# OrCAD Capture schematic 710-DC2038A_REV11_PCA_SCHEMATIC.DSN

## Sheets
1 PAGE2: size Custom; note: 35V/3.2A MULTI-CELL STEP-DOWN BATTERY CHARGER WITH POWERPATH AND I2C TELEMETRY
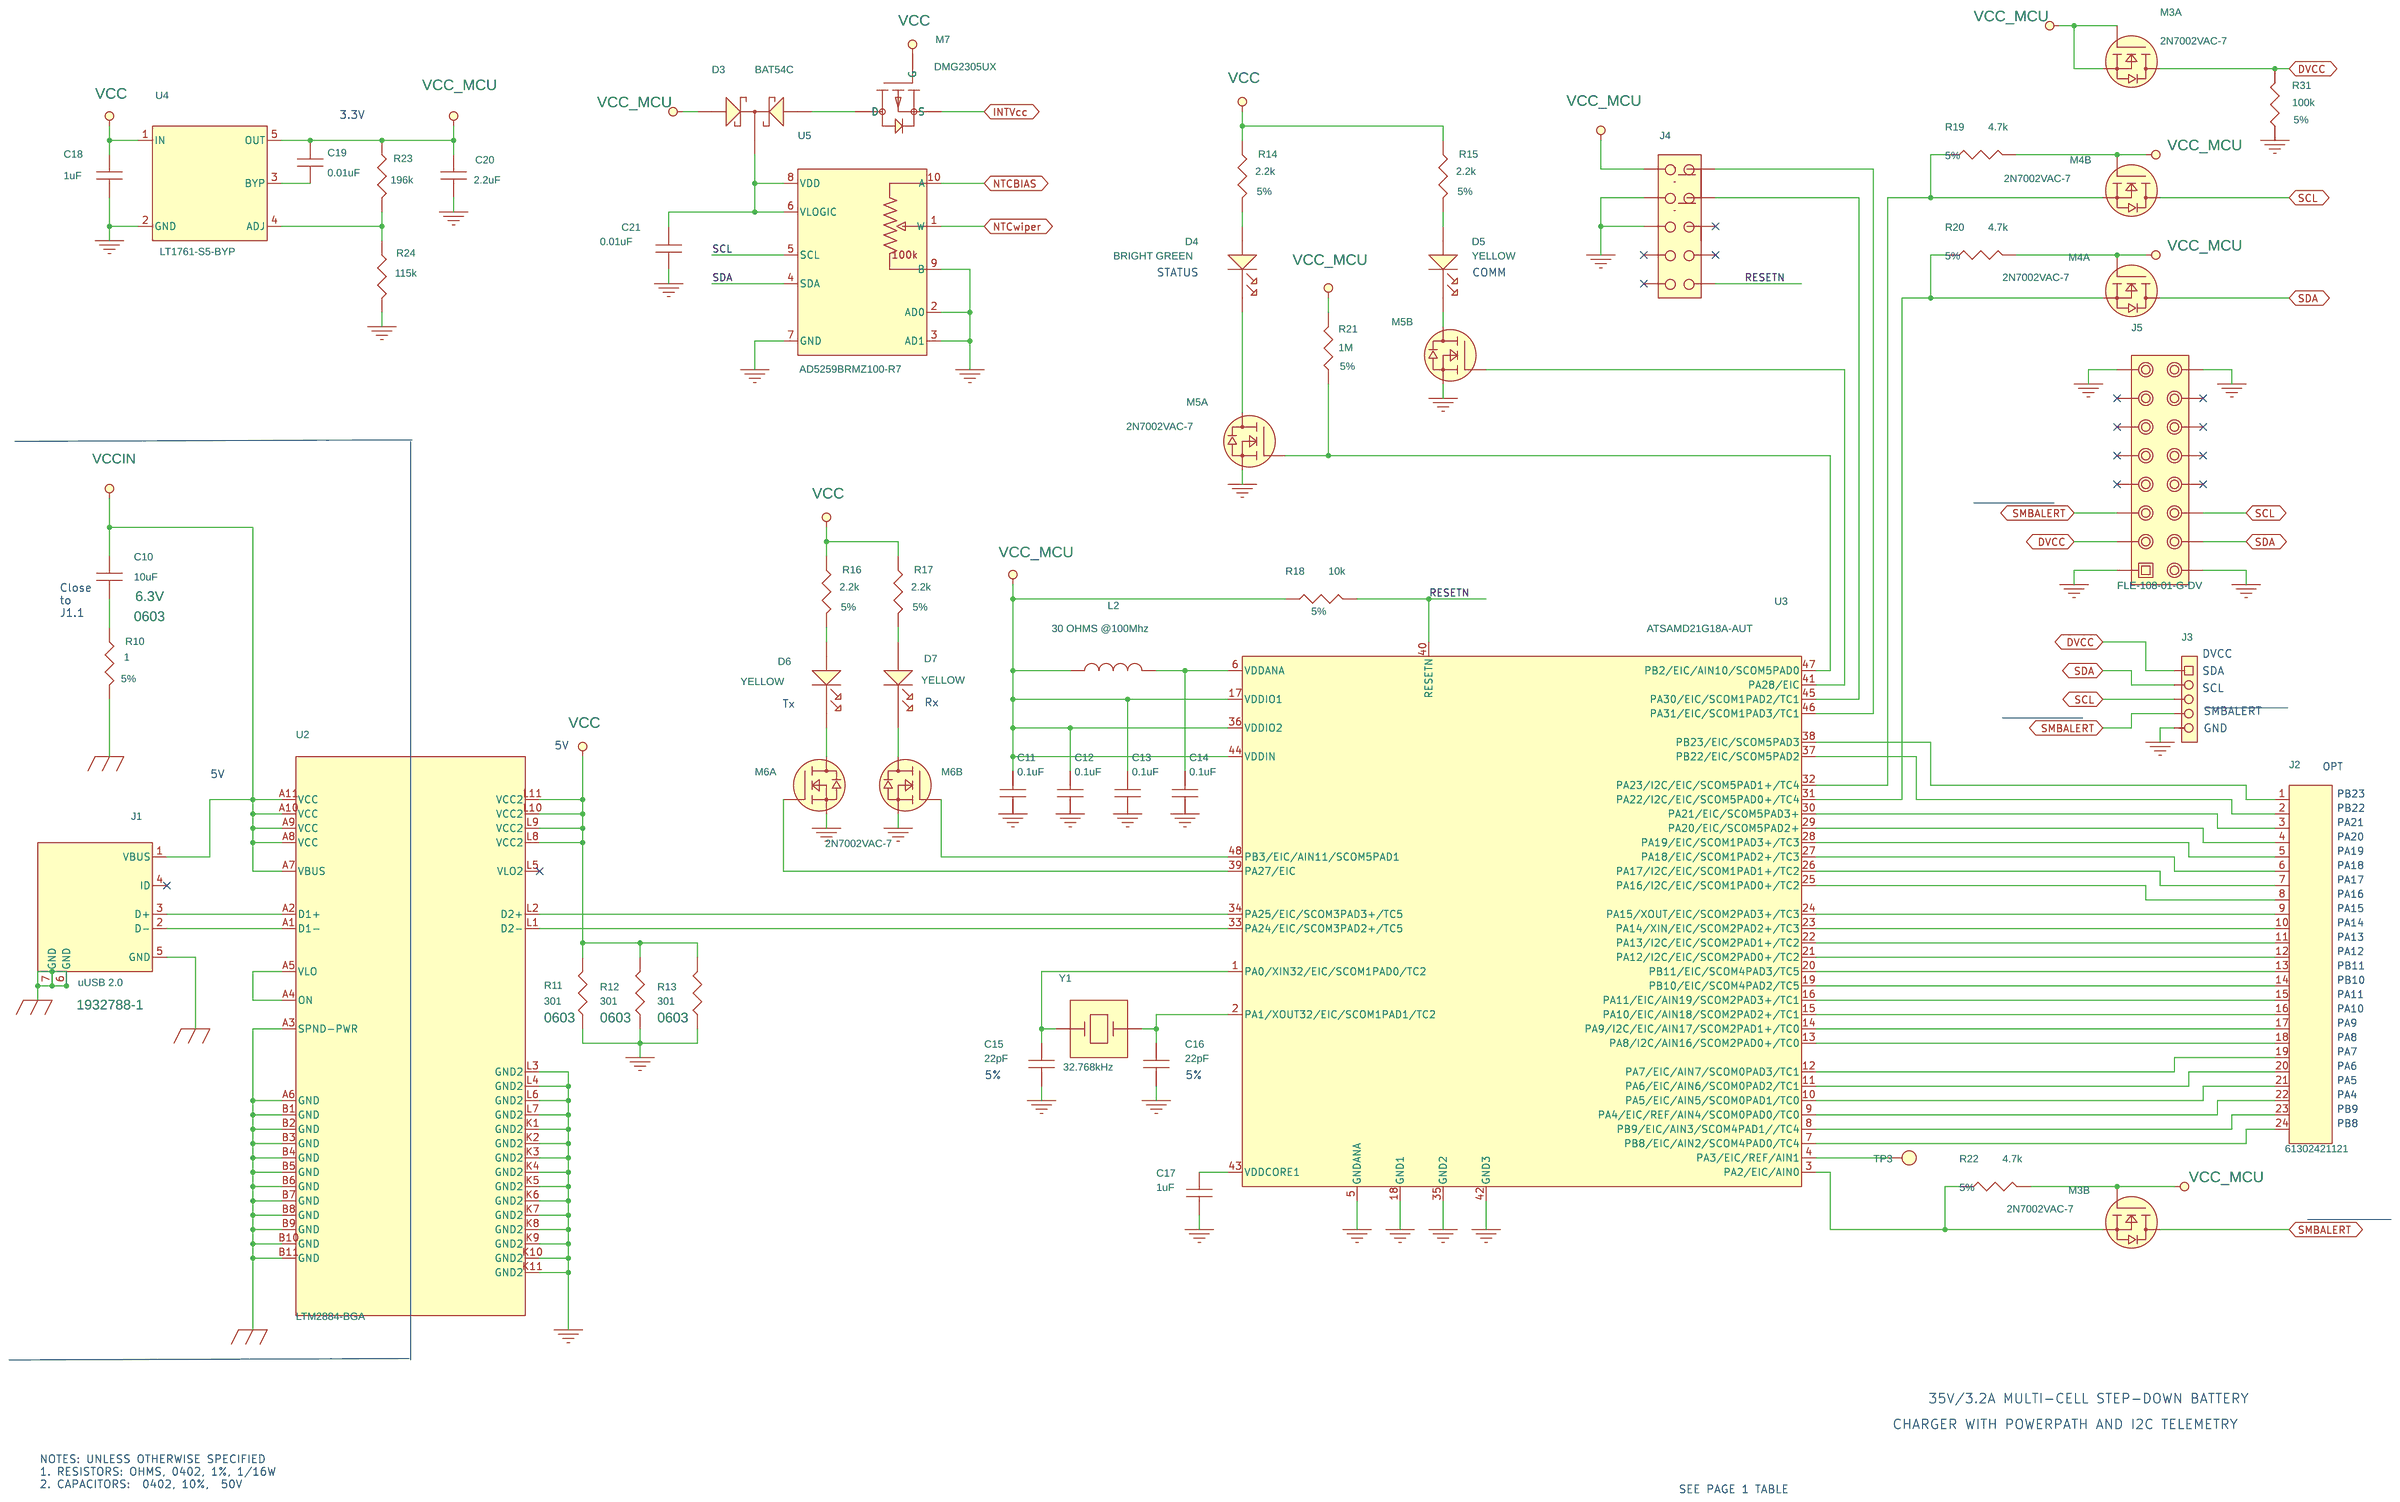
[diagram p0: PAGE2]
2 PAGE 1: size C
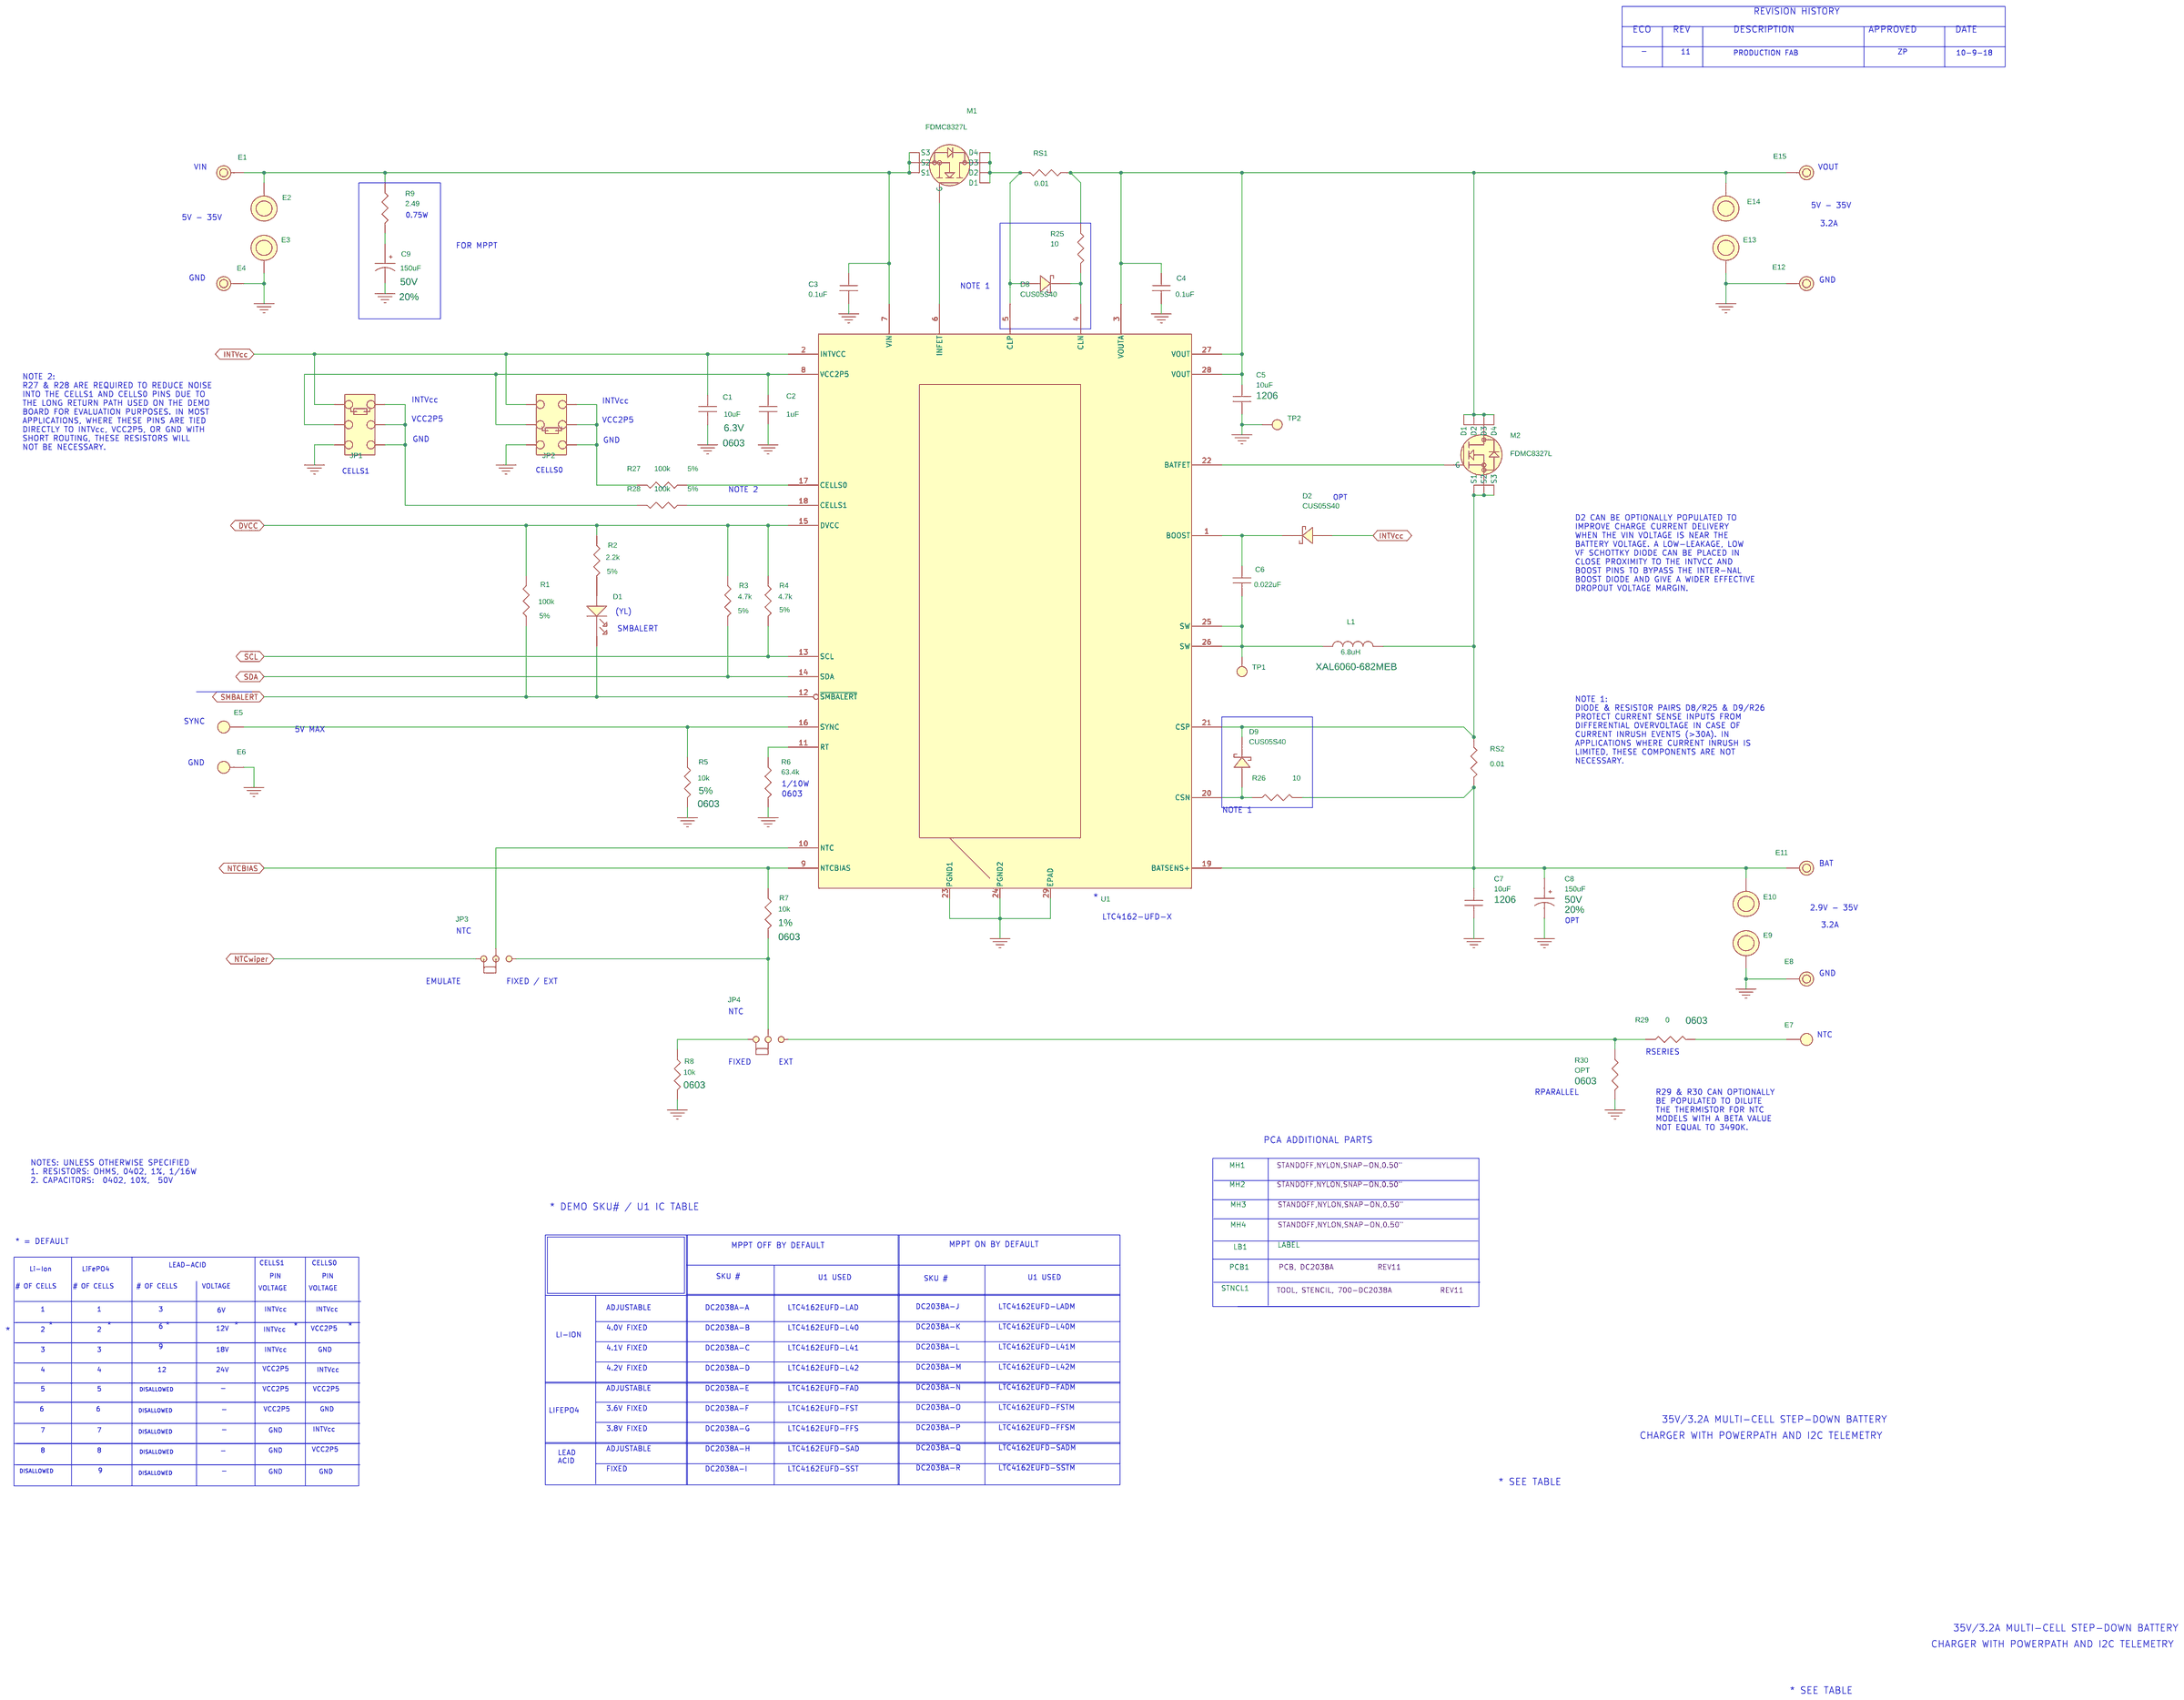
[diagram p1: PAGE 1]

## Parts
sheet PAGE2
C10  10uF  [CC0603N]
C11  0.1uF  [CC0402N]
C12  0.1uF  [CC0402N]
C13  0.1uF  [CC0402N]
C14  0.1uF  [CC0402N]
C15  22pF  [CC0402N]
C16  22pF  [CC0402N]
C17  1uF  [CC0402N]
C18  1uF  [CC0402N]
C19  0.01uF  [CC0402N]
C20  2.2uF  [CC0402N]
C21  0.01uF  [CC0402N]
D3  BAT54C  [SOT23-3M]
D4  BRIGHT GREEN  [LED_0603]
D5  YELLOW  [LED_0603]
D6  YELLOW  [LED_0603]
D7  YELLOW  [LED_0603]
J1  uUSB 2.0  [TE-1932788-1]
J2  61302421121  [WURTH-HDR-2.54MM-DUAL]
J3  HDR  [HDR-TSW-105-07-L-S]
J4  HDR  [WURTH-62201021121]
J5  SOCKET  [SAMTEC-FLE-108-01-XX-DV]
L2  30 OHMS @100Mhz  [IND0805N]
M3  2N7002VAC-7  [SOT563-6N]  (sections A,B)
M4  2N7002VAC-7  [SOT563-6N]  (sections A,B)
M5  2N7002VAC-7  [SOT563-6N]  (sections A,B)
M6  2N7002VAC-7  [SOT563-6N]  (sections A,B)
M7  DMG2305UX  [SOT23-3M]
R10  1  [CR0402M]
R11  301  [CR0603N]
R12  301  [CR0603N]
R13  301  [CR0603N]
R14  2.2k  [CR0402M]
R15  2.2k  [CR0402M]
R16  2.2k  [CR0402M]
R17  2.2k  [CR0402M]
R18  10k  [CR0402N]
R19  4.7k  [CR0402M]
R20  4.7k  [CR0402M]
R21  1M  [CR0402N]
R22  4.7k  [CR0402M]
R23  196k  [CR0603N]
R24  115k  [CR0603N]
R31  100k  [CR0402M]
TP3  TEST PAD  [PADSTYLE2]
U2  LTM2884-BGA  [LTM-BGA-44-1881]
U3  ATSAMD21G18A-AUT  [MICROCHIP-TQFP48-NO_TAB]
U4  LT1761-S5-BYP  [LTC-S5-5-1635]
U5  AD5259BRMZ100-R7  [AD5259BRMZ100-R7]
Y1  32.768kHz  [ECX-31B]
sheet PAGE 1
C1  10uF  [CC0603N]
C2  1uF  [CC0402M]
C3  0.1uF  [CC0402M]
C4  0.1uF  [CC0402M]
C5  10uF  [CC1206N]
C6  0.022uF  [CC0402M]
C7  10uF  [CC1206N]
C8  150uF  [CAP_EEFK_G]
C9  150uF  [CAP_EEFK_G]
D1  SUPER YELLOW  [LED_0603]
D2  CUS05S40  [SOD-323N]
D8  CUS05S40  [SOD-323N]
D9  CUS05S40  [SOD-323N]
E1  TEST POINT  [MILLMAX2501]
E2  BANANA JACK  [KEY-575-4]
E3  BANANA JACK  [KEY-575-4]
E4  TEST POINT  [MILLMAX2501]
E5  TEST POINT  [MILLMAX2308]
E6  TEST POINT  [MILLMAX2308]
E7  TEST POINT  [MILLMAX2308]
E8  TEST POINT  [MILLMAX2501]
E9  BANANA JACK  [KEY-575-4]
E10  BANANA JACK  [KEY-575-4]
E11  TEST POINT  [MILLMAX2501]
E12  TEST POINT  [MILLMAX2501]
E13  BANANA JACK  [KEY-575-4]
E14  BANANA JACK  [KEY-575-4]
E15  TEST POINT  [MILLMAX2501]
JP1  HDR  [CON6_2X3_WURTH_62130621021_SMT]
JP2  HDR  [CON6_2X3_WURTH_62130621021_SMT]
JP3  HDR.  [HD1X3-079]
JP4  HDR.  [HD1X3-079]
L1  6.8uH  [COILCRAFT-XAL6060]
LB1  LABEL  [895-0154_REV01]
M1  FDMC8327L  [FAIRCHILD-MLP3.3X3.3]
M2  FDMC8327L  [FAIRCHILD-MLP3.3X3.3]
MH1  STANDOFF  [KEYSTONE_8829-8834]
MH2  STANDOFF  [KEYSTONE_8829-8834]
MH3  STANDOFF  [KEYSTONE_8829-8834]
MH4  STANDOFF  [KEYSTONE_8829-8834]
PCB1  PCB, DC2038A
R1  100k  [CR0402M]
R2  2.2k  [CR0402M]
R3  4.7k  [CR0402M]
R4  4.7k  [CR0402M]
R5  10k  [CR0603N]
R6  63.4k  [CR0603N]
R7  10k  [CR0603N]
R8  10k  [CR0603N]
R9  2.49  [CR1206N]
R25  10  [CR0402N]
R26  10  [CR0402N]
R27  100k  [CR0402M]
R28  100k  [CR0402M]
R29  0  [CR0603N]
R30  OPT  [CR0603N]
RS1  0.01  [RES-PRL0816]
RS2  0.01  [RES-PRL0816]
STNCL1  TOOL, STENCIL, 700-DC2038A
TP1  TEST PAD  [PADSTYLE2]
TP2  TEST PAD  [PADSTYLE2]
U1  LTC4162-UFD-FADM  [LTC-UFD-28-1712]
XJP1  SHUNT
XJP2  SHUNT
XJP3  SHUNT
XJP4  SHUNT

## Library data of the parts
C1 C10 = CAP: CAP.,10uF,X5R,6.3V,20%,0603; CLASS: DISCRETE; Dielectric Type: X5R; Manufacturer: MURATA; Manufacturer PN: GRM188R60J106ME47D; PART_NUMBER: 150-3401; Package Size: 0603; Package Type: SMD; Rated Voltage: 6.3V; Tolerance: 20%
C11-C14 = CAP: CAP.,0.1uF,X5R,10V,20%,0402; CLASS: DISCRETE; Dielectric Type: X5R; Manufacturer: WURTH ELEKTRONIK; Manufacturer PN: 885012105010; PART_NUMBER: 150-2539; Package Size: 0402; Package Type: SMD; Rated Voltage: 10V; SIGNAL_MODEL: DEFAULT_CAPACITOR_100000pF_1_2; Temperature Coefficient: X5R; Tolerance: 20%
C15 C16 = CAP: CAP.,22pF,NP0,50V,5%,0402; CLASS: DISCRETE; Dielectric Type: NP0; Manufacturer: WURTH ELEKTRONIK; Manufacturer PN: 885012005057; PART_NUMBER: 150-2540; Package Size: 0402; Package Type: SMD; Rated Voltage: 50V; SIGNAL_MODEL: DEFAULT_CAPACITOR_22.000000pF_1_2; Temperature Coefficient: C0G, NP0; Tolerance: 5%
C17 C18 = CAP: CAP.,1uF,BJ,10V,20%,0402; CLASS: DISCRETE; Dielectric Type: BJ; FPLIST: CC0402N, CC0402M,CC0402L; Manufacturer: TDK; Manufacturer PN: CGB2A1JB1A105M033BC; PART_NUMBER: 150-2558; Package Size: 0402; Package Type: Surface Mount, MLCC; Rated Voltage: 10V; SIGNAL_MODEL: DEFAULT_CAPACITOR_1e+06pF_1_2; Temperature Coefficient: JB; Tolerance: 20%
C19 C21 = CAP: CAP.,0.01uF,X7R,25V,10%,0402; CLASS: DISCRETE; Dielectric Type: X7R; Manufacturer: WURTH ELEKTRONIK; Manufacturer PN: 885012205050; PART_NUMBER: 150-2542; Package Size: 0402; Package Type: SMD; Rated Voltage: 25V; SIGNAL_MODEL: DEFAULT_CAPACITOR_10000pF_1_2; Temperature Coefficient: X7R; Tolerance: 10%
C20 = CAP: CAP.,2.2uF,X5R,10V,20%,0402; CLASS: DISCRETE; Dielectric Type: X5R; Manufacturer: WURTH ELEKTRONIK; Manufacturer PN: 885012105013; PART_NUMBER: 150-2543; Package Size: 0402; Package Type: SMD; Rated Voltage: 10V; SIGNAL_MODEL: DEFAULT_CAPACITOR_2.2e+06pF_1_2; Temperature Coefficient: X5R; Tolerance: 20%
D3 = DIODE_SCHOTTKY_SOT_ARRAY_2_ALT: DIODE,SCHOTTKY,30V,200mA,SOT23; CLASS: DISCRETE; Manufacturer: DIODES INC.; Manufacturer PN: BAT54C-7-F; PART_NUMBER: 210-0084; Package Size: TO-236-3, SC-59, SOT-23-3; Package Type: SOT23; Rated Voltage: 30V
D4 = LED_ALT: LED,BRIGHT GREEN,WATERCLEAR,0603; CLASS: DISCRETE; FPLIST: LED_0603N,LED_0603L,LED_0603M; Manufacturer: WURTH ELEKTRONIK; Manufacturer PN: 150060VS75000; PART_NUMBER: 270-0072; Package Size: 0603 (1608 Metric); Package Type: 0603
D5-D7 = LED_ALT: LED,YELLOW,WATERCLEAR,0603; CLASS: DISCRETE; FPLIST: LED_0603N,LED_0603L,LED_0603M; Manufacturer: WURTH ELEKTRONIK; Manufacturer PN: 150060YS75000; PART_NUMBER: 270-0136; Package Size: 0603 (1608 Metric); Package Type: 0603
J1 = MICRO_USB_2.0: CONN.,uUSB 2.0,RCPT.,5 PINS, 1 PORT,Reverse Mount, R/A HORZ.,Type B, Flangeless; CLASS: IO; Manufacturer: TE CONNECTIVITY; Manufacturer PN: 1932788-1; PART_NUMBER: 250-0536
J2 = WURTH-61302421121: CONN HEADER VERT DUAL 24POS 2.54; CLASS: IO; Manufacturer: Wurth Electronics Inc.; Operating Temperature Minimum: -40C - 125C; PART_NUMBER: TMP-2425
J3 = HEADER_1X5: CONN.,HDR,MALE,1x5,2.54mm,VERT, STR, THT; CLASS: IO; Manufacturer: SAMTEC; Manufacturer PN: TSW-105-07-L-S; PART_NUMBER: 250-0599; Package Size: 0.230" (5.84mm)
J4 = HEADER_2X5_.100: CONN.,HDR,MALE,2x5,1.27mm,VERT, STR, THT; CLASS: IO; Manufacturer: WURTH ELEKTRONIK; Manufacturer PN: 62201021121; PART_NUMBER: 250-0763
J5 = HDR2X8_ALT1: CONN.,SOCKET,RCPT. FEMALE,2x8,1.27mm,VERT, STR, SMT,FLE Series; CLASS: IO; Manufacturer: SAMTEC; Manufacturer PN: FLE-108-01-G-DV; PART_NUMBER: 250-0764
L2 = FERRITEBEAD: IND.,30 OHMS @100Mhz,BEAD,6A,10mOHMS,0805; CLASS: DISCRETE; Manufacturer: TDK; Manufacturer PN: MPZ2012S300AT000; PART_NUMBER: 200-0237; Package Size: 0805
M3-M6 = 2N7002VAC-7: XSTR.,MOSFET, DUAL N-CH,0.28A,SOT-563; CLASS: DISCRETE; Manufacturer: DIODES INC.; PART_NUMBER: 240-0199; Package Size: SOT-563, SOT-666; Package Type: SOT-563; Polarity: 2 N-Channel (Dual); Rated Power: 150mW; Rated Voltage: 60V
M7 = 3P_P-CH_TYPE1A: XSTR.,MOSFET, P-CH,20V,4.2A,SOT23; CLASS: DISCRETE; Manufacturer: DIODES INC.; Manufacturer PN: DMG2305UX-13; PART_NUMBER: 240-0373; Package Size: SOT-23; Package Type: SOT23; Polarity: P-Channel; Rated Voltage: 20V
R10 = RES: RES.,1 OHM,5%,1/16W,0402,AEC-Q200; CLASS: DISCRETE; FPLIST: CR0402N,CR0402L,CR0402M; Manufacturer: KOA SPEER; Manufacturer PN: RK73B1ETTP1R0J; PART_NUMBER: 100-0208; Package Size: 0402; Rated Power: 1/16W; Temperature Coefficient: +/-200ppm; Tolerance: 5%
R11-R13 = RES: RES.,301 OHMS,1%,1/10W,0603,AEC-Q200; CLASS: DISCRETE; Manufacturer: PANASONIC; Manufacturer PN: ERJ3EKF3010V; PART_NUMBER: 100-0434; Package Size: 0603; Rated Power: 1/10W; Temperature Coefficient: 100ppm; Tolerance: 1%
R2 R14-R17 = RES: RES.,2.2k OHMS,5%,1/16W,0402,AEC-Q200; CLASS: DISCRETE; FPLIST: CR0402N,CR0402L,CR0402M; Manufacturer: VISHAY; Manufacturer PN: CRCW04022K20JNED; PART_NUMBER: 100-0324; Package Size: 0402; Rated Power: 1/16W; Temperature Coefficient: 200ppm; Tolerance: 5%
R18 = RES: RES.,10k OHMS,5%,1/16W,0402; CLASS: DISCRETE; FPLIST: CR0402N,CR0402L,CR0402M; Manufacturer: YAGEO; Manufacturer PN: RC0402JR-0710KL; PART_NUMBER: 100-0023; Package Size: 0402; Rated Power: 1/16W; SIGNAL_MODEL: DEFAULT_RESISTOR_10000OHM_1_2; Temperature Coefficient: 100ppm; Tolerance: 5%
R3 R4 R19 R20 R22 = RES: RES.,4.7k OHMS,5%,1/16W,0402,AEC-Q200; CLASS: DISCRETE; FPLIST: CR0402N,CR0402L,CR0402M; Manufacturer: NIC; Manufacturer PN: NRC04J472TRF; PART_NUMBER: 100-0216; Package Size: 0402; Rated Power: 1/16W; Temperature Coefficient: 200ppm; Tolerance: 5%
R21 = RES: RES.,1M OHM,5%,1/16W,0402,AEC-Q200; CLASS: DISCRETE; FPLIST: CR0402N,CR0402L,CR0402M; Manufacturer: VISHAY; Manufacturer PN: CRCW04021M00JNED; PART_NUMBER: 100-0321; Package Size: 0402; Rated Power: 1/16W; SIGNAL_MODEL: DEFAULT_RESISTOR_0.001OHM_1_2; Temperature Coefficient: 200ppm; Tolerance: 5%
R23 = RES: RES.,196k OHMS,1%,1/10W,0603; CLASS: DISCRETE; FPLIST: CR0603N,CR0603L,CR0603M; Manufacturer: VISHAY; Manufacturer PN: CRCW0603196KFKEA; PART_NUMBER: 100-2660; Package Size: 0603; Rated Power: 1/10W; Temperature Coefficient: 100ppm/C; Tolerance: 1%
R24 = RES: RES.,115k OHMS,1%,1/10W,0603; CLASS: DISCRETE; FPLIST: CR0603N,CR0603L,CR0603M; Manufacturer: NIC; Manufacturer PN: NRC06F1153TRF; PART_NUMBER: 100-2580; Package Size: 0603; Rated Power: 1/10W; Temperature Coefficient: 100ppm; Tolerance: 1%
R1 R27 R28 R31 = RES: RES.,100k OHMS,5%,1/16W,0402,AEC-Q200; CLASS: DISCRETE; FPLIST: CR0402N,CR0402L,CR0402M; Manufacturer: NIC; Manufacturer PN: NRC04J104TRF; PART_NUMBER: 100-0359; Package Size: 0402; Rated Power: 1/16W; Temperature Coefficient: 200ppm/C; Tolerance: 5%
TP1-TP3 = PAD_STYLE_E: TESTPOINT, PCB COPPER FEATURE; CLASS: IO; FPLIST: PADSTYLE1,PADSTYLE2,PADSTYLE3,PADSTYLE4,PADSTYLE5,PADSTYLE6,PADSTYLE7,PADSTYLE8; PART_NUMBER: PCBPADS-8
U2 = LTM2884-BGA: IC,Isolated USB Transceiver,BGA-44; CLASS: IC; Manufacturer: LINEAR TECH.; Manufacturer PN: LTM2884CY#PBF; PART_NUMBER: LTM2884CY#PBF; Package Type: BGA-44
U3 = ATSAMD21G18A-AUT: IC, MEMORY,MCU,32BIT, 256KB FLASH,TQFP48; CLASS: IC; FPLIST: MICROCHIP-TQFP48,MICROCHIP-TQFP48-NO_TAB; Manufacturer: MICROCHIP; PART_NUMBER: 380-0098; Package Size: 48-TQFP; Package Type: TQFP48; Supply Voltage: 1.62 V - 3.6 V
U4 = LT1761-S5-BYP_ALT1: IC,REG LDO ADJ, 100mA,TSOT23-5; CLASS: IC; Manufacturer: LINEAR TECH.; Manufacturer PN: LT1761ES5-BYP#PBF; PART_NUMBER: LT1761ES5-BYP#PBF; Package Size: TSOT-23; Package Type: TSOT23-5
U5 = ANALOG-AD5259BRMZ100-R7: IC,POT DGTL, 100k OHMS, 256POS,MSOP-10,Nonvolatile, I2C-Compatible; CLASS: IC; Manufacturer: Analog Devices Inc.; PART_NUMBER: 280-0615; Package Size: 10-TFSOP, 10-MSOP (0.118", 3.00mm Width); Package Type: MSOP-10; Supply Voltage: 2.7 V - 5.5 V
Y1 = XTAL_B: CRYSTAL,32.768kHz,12.5pF,3.2x1.5mm SMD; CLASS: DISCRETE; Frequency Tolerance: 20ppm; Manufacturer: ABRACON; Manufacturer PN: ABS07-32.768kHz-4-T; PART_NUMBER: 340-0066; Package Size: 0.126" L x 0.059" W (3.20mm x 1.50mm)
C2 = CAP: CAP.,1uF,X5R,16V,10%,0402; CLASS: DISCRETE; Dielectric Type: X5R; FPLIST: CC0402N,CC0402L,CC0402M; Manufacturer: AVX; Manufacturer PN: 0402YD105KAT2A; PART_NUMBER: 150-0250; Package Size: 0402; Rated Voltage: 16V; Tolerance: 10%
C3 C4 = CAP: CAP.,0.1uF,X7R,50V,10%,0402; CLASS: DISCRETE; Dielectric Type: X7R; FPLIST: CC0402N,CC0402L,CC0402M; Manufacturer: AVX; Manufacturer PN: 04025C104KAT2A; PART_NUMBER: 150-3240; Package Size: 0402; Package Type: SMD; Rated Voltage: 50V; Tolerance: 10%
C5 C7 = CAP: CAP.,10uF,X5R,50V,10%,1206; CLASS: DISCRETE; Dielectric Type: X5R; Manufacturer: MURATA; Manufacturer PN: GRM31CR61H106KA12L; PART_NUMBER: 150-0330; Package Size: 1206; Rated Voltage: 50V; Tolerance: 10%
C6 = CAP: CAP.,0.022uF,X7R,16V,10%,0402; CLASS: DISCRETE; Dielectric Type: X7R; FPLIST: CC0402N,CC0402L,CC0402M; Manufacturer: AVX; Manufacturer PN: 0402YC223KAT2A; PART_NUMBER: 150-0361; Package Size: 0402; Rated Voltage: 16V; Tolerance: 10%
C8 C9 = CAP_P_ALT: CAP.,150uF,ALUM. ELECT.,50V,20%,10x10.2mm RADIAL,FK Series, AEC-Q200; CLASS: DISCRETE; Dielectric Type: ALUM. ELECT.; Manufacturer: PANASONIC; Manufacturer PN: EEEFK1H151P; PART_NUMBER: 150-2438; Package Size: 10x10.2mm RADIAL; Package Type: Radial; Rated Voltage: 50V; Tolerance: 20%; UserField01: AEC-Q200
D1 = LED_ALT: LED,SUPER YELLOW,MILKY WHITE DIFF.,0603; CLASS: DISCRETE; Manufacturer: LUMEX; Manufacturer PN: SML-LX0603SYW-TR; PART_NUMBER: 270-0090; Package Size: 0603 (1608 Metric); Package Type: 0603
D2 D8 D9 = DIODE_SCHOTTKY_A_ALT: DIODE,SCHOTTKY,40V,500mA,USC (SOD-323); CLASS: DISCRETE; Manufacturer: TOSHIBA; Manufacturer PN: CUS05S40,H3F; PART_NUMBER: 210-0262; Package Type: USC (SOD-323); Rated Voltage: 40V
E1 E4 E8 E11 E12 E15 = TESTPOINT_.219_MILL-MAX_2501: TEST POINT,TURRET,0.094" MTG. HOLE,PCB 0.062" THICK; CLASS: IO; Manufacturer: MILL-MAX; Manufacturer PN: 2501-2-00-80-00-00-07-0; PART_NUMBER: 260-0003
E2 E3 E9 E10 E13 E14 = BANANA_KEYSTONE-575-4: CONN.,BANANA JACK,FEMALE,THT,NON-INSULATED,SWAGE,0.218"; CLASS: IO; Manufacturer: KEYSTONE; Manufacturer PN: 575-4; PART_NUMBER: 250-0428
E5-E7 = TEST_POINT_.156_MILL-MAX_2308: TEST POINT,TURRET,0.064" MTG. HOLE,PCB 0.062" THICK; CLASS: IO; Manufacturer: MILL-MAX; Manufacturer PN: 2308-2-00-80-00-00-07-0; PART_NUMBER: 260-0004
JP1 JP2 = HDR2X3: CONN.,HDR,MALE,2x3,1.27mm,VERT, STR, SMT; CLASS: IO; Manufacturer: WURTH ELEKTRONIK; Manufacturer PN: 62130621021; PART_NUMBER: 250-0590
JP3 JP4 = HDR3X1_A: CONN.,HDR.,MALE,1x3,2mm,VERT, STR, THT,10u" AU; CLASS: IO; Manufacturer: SAMTEC; Manufacturer PN: TMM-103-02-L-S; PART_NUMBER: 250-0422
L1 = IND_ALT: IND.,6.8uH,PWR, SHIELDED,20%,9A,20.80mOHMS,6.56mmX6.36mm,AEC-Q200, XAL6060; CLASS: DISCRETE; Manufacturer: Coilcraft; Manufacturer PN: XAL6060-682MEB; PART_NUMBER: 200-0205; Package Size: 6.56mmX6.36mm; Tolerance: 20%
LB1 = BLANK_LABEL: LABEL SPEC, DEMO BOARD SERIAL NUMBER; Manufacturer: BRADY; Manufacturer PN: THT-96-717-10; PART_NUMBER: 895-0154
M1 M2 = 8P_N-CH_TYPE1B: XSTR.,MOSFET, N-CH,40V,14A,Power 33 (MLP 3.3Ax3.3) 8L; CLASS: DISCRETE; Manufacturer: ON SEMICONDUCTOR; PART_NUMBER: 240-0151; Package Type: Power 33 (MLP 3.3Ax3.3) 8L; Rated Voltage: 40V
MH1-MH4 = BLANK_MECHANICAL_PART: STANDOFF,NYLON,SNAP-ON,0.50"; CLASS: MECHANICAL PART; Manufacturer: KEYSTONE; Manufacturer PN: 8833; PART_NUMBER: 763-0007
PCB1 = BLANK_PCB_PART: BOM Notes: REV11; CLASS: DISCRETE; Manufacturer: GORILLA CIRCUITS; Manufacturer PN: 600-DC2038A; PART_NUMBER: 600-DC2038A
R5 = RES: RES.,10k OHMS,5%,1/10W,0603,AEC-Q200; CLASS: DISCRETE; Manufacturer: NIC; Manufacturer PN: NRC06J103TRF; PART_NUMBER: 100-2013; Package Size: 0603; Rated Power: 1/10W; Temperature Coefficient: 200ppm/C; Tolerance: 5%
R6 = RES: RES.,63.4k OHMS,1%,1/10W,0603,AEC-Q200; CLASS: DISCRETE; FPLIST: CR0603N,CR0603L,CR0603M; Manufacturer: VISHAY; Manufacturer PN: CRCW060363K4FKEA; PART_NUMBER: 100-2523; Package Size: 0603; Rated Power: 1/10W; Temperature Coefficient: +/-100ppm; Tolerance: 1%
R7 R8 = RES: RES.,10k OHMS,1%,1/10W,0603,AEC-Q200; CLASS: DISCRETE; Manufacturer: VISHAY; Manufacturer PN: CRCW060310K0FKEA; PART_NUMBER: 100-2012; Package Size: 0603; Rated Power: 1/10W; Temperature Coefficient: +/-100ppm/C; Tolerance: 1%
R9 = RES: RES.,2.49 OHMS,1%,3/4W,1206,PULSE PROOF HIGH PWR, AEC-Q200; CLASS: DISCRETE; FPLIST: CR1206N,CR1206L,CR1206M; Manufacturer: VISHAY; Manufacturer PN: CRCW12062R49FKEAHP; PART_NUMBER: 100-2447; Package Size: 1206; Rated Power: 3/4W; Temperature Coefficient: 100ppm; Tolerance: 1%
R25 R26 = RES: RES.,10 OHMS,1%,1/16W,0402,AEC-Q200; CLASS: DISCRETE; FPLIST: CR0402N,CR0402L,CR0402M; Manufacturer: NIC; Manufacturer PN: NRC04F10R0TRF; PART_NUMBER: 100-0325; Package Size: 0402; Rated Power: 1/16W; Temperature Coefficient: 100ppm; Tolerance: 1%
R29 = RES: RES.,0 OHM,1/10W,0603,1A, AEC-Q200; CLASS: DISCRETE; FPLIST: CR0603N,CR0603L,CR0603M; Manufacturer: ROHM; Manufacturer PN: MCR03EZPJ000; PART_NUMBER: 100-0195; Package Size: 0603; Rated Power: 1/10W
R30 = RES: RES., OPTION, 0603; CLASS: DISCRETE; FPLIST: CR0603N,CR0603L,CR0603M; PART_NUMBER: 100-2374; Package Size: 0603
RS1 RS2 = RES: RES.,0.01 OHM,1%,1/3W,0603, LONG-SIDE TERM.,SENSE; CLASS: DISCRETE; Manufacturer: SUSUMU; Manufacturer PN: PRL0816-R010-F-T1; PART_NUMBER: 100-0490; Package Size: 0603, LONG-SIDE TERM.; Rated Power: 1/3W; Temperature Coefficient: 0 to 330ppm; Tolerance: 1%
STNCL1 = BLANK_STENCIL_PART: BOM Notes: REV11; CLASS: DISCRETE; Manufacturer: LINEAR TECH.; Manufacturer PN: 830-DC2038A; PART_NUMBER: 830-DC2038A
U1 = LTC4162-UFD-X: IC,Multi-Cell LiFePO4 Batt. Chrgr,QFN-28(UFD),35V/3.2A, I2C Adj.V. MPPT ON; CLASS: IC; Manufacturer: LINEAR TECH.; Manufacturer PN: LTC4162EUFD-FADM#PBF; PART_NUMBER: LTC4162EUFD-FADM#PBF; Package Size: QFN-28; Package Type: QFN-28(UFD)
XJP1 XJP2 = SHUNT_D: CONN.,SHUNT,FEMALE,1x2,1.27mm; CLASS: IO; Manufacturer: WURTH ELEKTRONIK; Manufacturer PN: 622002115121; PART_NUMBER: 250-0591
XJP3 XJP4 = CONN_SHUNT_2_POS_2mm: CONN.,SHUNT,FEMALE,2 POS,2mm; CLASS: IO; Manufacturer: Wurth Elektronik; Manufacturer PN: 60800213421; PART_NUMBER: 250-0485

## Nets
DVCC: J3.1 J5.3 M3.6(D) R1.2 R2.1 R3.1 R4.1 R31.2 U1.15(DVCC)
GND: C1.2 C2.2 C3.2 C4.2 C5.2 C7.2 C8.2 C9.2 C11.1 C12.1 C13.1 C14.1 C15.2 C16.2 C17.2 C18.2 C20.2 C21.1 E3.1 E4.1 E6.1(A) E8.1 E9.1 E12.1 E13.1 J3.5 J4.3 J4.5 J5.1 J5.2 J5.15 J5.16 JP1.5 JP2.6 M5.2(S) M5.5(S) M6.2(S) M6.5(S) R5.2 R6.2 R8.2 R11.1 R12.1 R13.1 R24.2 R30.2 R31.1 TP2.1(TP) U1.23(PGND1) U1.24(PGND2) U1.29(EPAD) U2.K1(GND2) U2.K2(GND2) U2.K3(GND2) U2.K4(GND2) U2.K5(GND2) U2.K6(GND2) U2.K7(GND2) U2.K8(GND2) U2.K9(GND2) U2.K10(GND2) U2.K11(GND2) U2.L3(GND2) U2.L4(GND2) U2.L6(GND2) U2.L7(GND2) U3.5(GNDANA) U3.18(GND1) U3.35(GND2) U3.42(GND3) U4.2(GND) U5.2(AD0) U5.3(AD1) U5.7(GND) U5.9(B)
GND_EARTH: J1.5(GND) J1.6(GND) J1.7(GND) R10.2 U2.A3(SPND-PWR) U2.A6(GND) U2.B1(GND) U2.B2(GND) U2.B3(GND) U2.B4(GND) U2.B5(GND) U2.B6(GND) U2.B7(GND) U2.B8(GND) U2.B9(GND) U2.B10(GND) U2.B11(GND)
Vcc: C18.1 M7.1(G) R11.2 R12.2 R13.2 R14.1 R15.1 R16.1 R17.1 U2.L8(VCC2) U2.L9(VCC2) U2.L10(VCC2) U2.L11(VCC2) U4.1(IN)
Vcc_MCU: C11.2 C12.2 C13.2 C19.2 C20.1 D3.2 J4.1 L2.1 M3.1(G) M3.2(S) M3.4(G) M4.1(G) M4.4(G) R18.2 R19.2 R20.2 R21.2 R22.2 R23.1 U3.17(VDDIO1) U3.36(VDDIO2) U3.44(VDDIN) U4.5(OUT)
VCCin: C10.1 J1.1(VBUS) U2.A7(VBUS) U2.A8(VCC) U2.A9(VCC) U2.A10(VCC) U2.A11(VCC)
INTVcc: C1.1 D2.2(A) JP1.1 JP2.2 M7.2(S) U1.2(INTVCC)
NTCBIAS: R7.1 U1.9(NTCBIAS) U5.10(A)
NTCwiper: JP3.1 U5.1(W)
RESETN: J4.10 R18.1 U3.40(RESETN)
SCL: J3.3 J5.6 M4.3(D) R4.2 U1.13(SCL) U5.5(SCL)
SDA: J3.2 J5.4 M4.6(D) R3.2 U1.14(SDA) U5.4(SDA)
SMBALERT: D1.1(CATHODE) J3.4 J5.5 M3.3(D) R1.1 U1.12(~{SMBALERT})
N17025509: JP2.1 JP2.3 JP2.5 R27.2
N17025513: JP1.2 JP1.4 JP1.6 R28.2
N17025541: R6.1 U1.11(RT)
N17025643: C3.1 E1.1 E2.1 M1.1(S1) M1.2(S2) M1.3(S3) R9.1 U1.7(VIN)
N17025991: C2.1 JP1.3 JP2.4 U1.8(VCC2P5)
N17100315: U2.A4(ON) U2.A5(VLO)
N17100321: C10.2 R10.1
N17100323: J1.2(D-) U2.A1(D1-)
N17100355: J1.3(D+) U2.A2(D1+)
N17100734: C21.2 D3.3 U5.6(VLOGIC) U5.8(VDD)
N17100949: U2.L1(D2-) U3.33(PA24/EIC/SCOM3PAD2+/TC5)
N17100951: U2.L2(D2+) U3.34(PA25/EIC/SCOM3PAD3+/TC5)
N17178542: C9.1 R9.2
N17227771: E5.1(A) R5.1 U1.16(SYNC)
N17228764: JP4.1 R8.1
N17228766: JP4.3 R29.1 R30.1
N17228779: JP3.3 JP4.2 R7.2
N17228787: JP3.2 U1.10(NTC)
N17252381: C14.2 L2.2 U3.6(VDDANA)
N17252406: M5.1(G) R21.1 U3.47(PB2/EIC/AIN10/SCOM5PAD0)
N17252432: M4.5(S) R19.1 U3.32(PA23/I2C/EIC/SCOM5PAD1+/TC4)
N17252439: M4.2(S) R20.1 U3.31(PA22/I2C/EIC/SCOM5PAD0+/TC4)
N17252441: D5.2(ANODE) R15.2
N17252443: D4.2(ANODE) R14.2
N17252445: D5.1(CATHODE) M5.3(D)
N17252447: D4.1(CATHODE) M5.6(D)
N17252461: M5.4(G) U3.41(PA28/EIC)
N17252463: M3.5(S) R22.1 U3.3(PA2/EIC/AIN0)
N17252485: TP3.1(TP) U3.4(PA3/EIC/REF/AIN1)
N17252498: J2.3 U3.30(PA21/EIC/SCOM5PAD3+)
N17252504: J2.4 U3.29(PA20/EIC/SCOM5PAD2+)
N17252508: J2.5 U3.28(PA19/EIC/SCOM1PAD3+/TC3)
N17252512: J2.6 U3.27(PA18/EIC/SCOM1PAD2+/TC3)
N17252516: J2.7 U3.26(PA17/I2C/EIC/SCOM1PAD1+/TC2)
N17252524: J2.8 U3.25(PA16/I2C/EIC/SCOM1PAD0+/TC2)
N17252542: J2.9 U3.24(PA15/XOUT/EIC/SCOM2PAD3+/TC3)
N17252556: J2.10 U3.23(PA14/XIN/EIC/SCOM2PAD2+/TC3)
N17252558: J2.13 U3.20(PB11/EIC/SCOM4PAD3/TC5)
N17252560: J2.14 U3.19(PB10/EIC/SCOM4PAD2/TC5)
N17252562: J2.15 U3.16(PA11/EIC/AIN19/SCOM2PAD3+/TC1)
N17252564: J2.16 U3.15(PA10/EIC/AIN18/SCOM2PAD2+/TC1)
N17252566: J2.17 U3.14(PA9/I2C/EIC/AIN17/SCOM2PAD1+/TC0)
N17252572: J2.18 U3.13(PA8/I2C/AIN16/SCOM2PAD0+/TC0)
N17252578: J2.19 U3.12(PA7/EIC/AIN7/SCOM0PAD3/TC1)
N17252584: J2.20 U3.11(PA6/EIC/AIN6/SCOM0PAD2/TC1)
N17252590: J2.21 U3.10(PA5/EIC/AIN5/SCOM0PAD1/TC0)
N17252598: J4.4 U3.45(PA30/EIC/SCOM1PAD2/TC1)
N17252646: J2.11 U3.22(PA13/I2C/EIC/SCOM2PAD1+/TC2)
N17252652: J2.12 U3.21(PA12/I2C/EIC/SCOM2PAD0+/TC2)
N17252674: J2.22 U3.9(PA4/EIC/REF/AIN4/SCOM0PAD0/TC0)
N17252680: J2.23 U3.8(PB9/EIC/AIN3/SCOM4PAD1//TC4)
N17252686: C17.1 U3.43(VDDCORE1)
N17252690: J2.24 U3.7(PB8/EIC/AIN2/SCOM4PAD0/TC4)
N17252778: C16.1 U3.2(PA1/XOUT32/EIC/SCOM1PAD1/TC2) Y1.2
N17252780: C15.1 U3.1(PA0/XIN32/EIC/SCOM1PAD0/TC2) Y1.1
N17252790: J4.2 U3.46(PA31/EIC/SCOM1PAD3/TC1)
N17252850: D6.2(ANODE) R16.2
N17252852: D7.2(ANODE) R17.2
N17252860: D6.1(CATHODE) M6.6(D)
N17252862: D7.1(CATHODE) M6.3(D)
N17253077: M6.1(G) U3.39(PA27/EIC)
N17253079: M6.4(G) U3.48(PB3/EIC/AIN11/SCOM5PAD1)
N17258071: R23.2 R24.1 U4.4(ADJ)
N17258103: C19.1 U4.3(BYP)
N17284427: C7.1 C8.1 E10.1 E11.1 R26.2 RS2.2 U1.19(BATSENS+)
N17284465: D9.1(C) L1.1 M2.1(S1) M2.2(S2) M2.3(S3) RS2.1 U1.21(CSP)
N17284471: M2.4(G) U1.22(BATFET)
N17284475: C4.1 C5.1 E14.1 E15.1 M2.5(D1) M2.6(D2) M2.7(D3) M2.8(D4) R25.1 RS1.1 U1.3(VOUTA) U1.27(VOUT) U1.28(VOUT)
N17284481: C6.2 L1.2 TP1.1(TP) U1.25(SW) U1.26(SW)
N17284497: M1.4(G) U1.6(INFET)
N17284519: D9.2(A) R26.1 U1.20(CSN)
N17284550: D8.2(A) M1.5(D1) M1.6(D2) M1.7(D3) M1.8(D4) RS1.2 U1.5(CLP)
N17284674: C6.1 D2.1(C) U1.1(BOOST)
N17294807: D8.1(C) R25.2 U1.4(CLN)
N17306726: J2.2 U3.37(PB22/EIC/SCOM5PAD2)
N17306735: J2.1 U3.38(PB23/EIC/SCOM5PAD3)
N17340317: E7.1(A) R29.2
N17341383: R27.1 U1.17(CELLS0)
N17341425: R28.1 U1.18(CELLS1)
N17349390: D3.1 M7.3(D)
N17366524: D1.2(ANODE) R2.2

Not connected (* = marked no-connect by the designer): J1 4(ID)*; J4 6* 7* 8* 9*; J5 7* 8* 9* 10* 11* 12* 13* 14*; U2 L5(VLO2)*

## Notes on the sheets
sheet 1
- 3.3V
- STATUS
- COMM
- Close
  to
  J1.1
- DVCC
- SDA
- SCL
- Tx
- Rx
- SMBALERT
- GND
- 5V
- OPT
- 5V
- PB23
- PB22
- PA21
- PA19
- PA20
- PA18
- PA17
- PA16
- PA15
- PA13
- PA14
- PA12
- PB11
- PB10
- PA11
- PA10
- PA8
- PA9
- PA7
- PA6
- 5%
- 5%
- PA5
- PA4
- PB8
- PB9
- 35V/3.2A MULTI-CELL STEP-DOWN BATTERY
- CHARGER WITH POWERPATH AND I2C TELEMETRY
- NOTES: UNLESS OTHERWISE SPECIFIED
  1. RESISTORS: OHMS, 0402, 1%, 1/16W
  2. CAPACITORS:  0402, 10%,  50V
- SEE PAGE 1 TABLE
sheet 2
- REVISION HISTORY
- ECO
- REV
- DESCRIPTION
- APPROVED
- DATE
- -
- 11
- PRODUCTION FAB
- ZP
- 10-9-18
- VIN
- VOUT
- 5V - 35V
- 5V - 35V
- 0.75W
- 3.2A
- FOR MPPT
- GND
- GND
- NOTE 1
- NOTE 2:
  R27 & R28 ARE REQUIRED TO REDUCE NOISE
  INTO THE CELLS1 AND CELLS0 PINS DUE TO
  THE LONG RETURN PATH USED ON THE DEMO
  BOARD FOR EVALUATION PURPOSES. IN MOST
  APPLICATIONS, WHERE THESE PINS ARE TIED
  DIRECTLY TO INTVcc, VCC2P5, OR GND WITH
  SHORT ROUTING, THESE RESISTORS WILL
  NOT BE NECESSARY.
- INTVcc
- INTVcc
- VCC2P5
- VCC2P5
- GND
- GND
- CELLS1
- CELLS0
- NOTE 2
- OPT
- D2 CAN BE OPTIONALLY POPULATED TO
  IMPROVE CHARGE CURRENT DELIVERY
  WHEN THE VIN VOLTAGE IS NEAR THE
  BATTERY VOLTAGE. A LOW-LEAKAGE, LOW
  VF SCHOTTKY DIODE CAN BE PLACED IN
  CLOSE PROXIMITY TO THE INTVCC AND
  BOOST PINS TO BYPASS THE INTER-NAL
  BOOST DIODE AND GIVE A WIDER EFFECTIVE
  DROPOUT VOLTAGE MARGIN.
- (YL)
- SMBALERT
- NOTE 1:
  DIODE & RESISTOR PAIRS D8/R25 & D9/R26
  PROTECT CURRENT SENSE INPUTS FROM
  DIFFERENTIAL OVERVOLTAGE IN CASE OF
  CURRENT INRUSH EVENTS (>30A). IN
  APPLICATIONS WHERE CURRENT INRUSH IS
  LIMITED, THESE COMPONENTS ARE NOT
  NECESSARY.
- SYNC
- 5V MAX
- GND
- 0603
- 1/10W
- NOTE 1
- BAT
- *
- 2.9V - 35V
- LTC4162-UFD-X
- OPT
- 3.2A
- NTC
- EMULATE
- FIXED / EXT
- GND
- NTC
- NTC
- RSERIES
- FIXED
- EXT
- RPARALLEL
- R29 & R30 CAN OPTIONALLY
  BE POPULATED TO DILUTE
  THE THERMISTOR FOR NTC
  MODELS WITH A BETA VALUE
  NOT EQUAL TO 3490K.
- PCA ADDITIONAL PARTS
- NOTES: UNLESS OTHERWISE SPECIFIED
  1. RESISTORS: OHMS, 0402, 1%, 1/16W
  2. CAPACITORS:  0402, 10%,  50V
- * DEMO SKU# / U1 IC TABLE
- * = DEFAULT
- MPPT OFF BY DEFAULT
- MPPT ON BY DEFAULT
- Li-Ion
- LiFePO4
- LEAD-ACID
- CELLS1
- CELLS0
- PIN
- PIN
- SKU #
- U1 USED
- SKU #
- U1 USED
- # OF CELLS
- # OF CELLS
- # OF CELLS
- VOLTAGE
- VOLTAGE
- VOLTAGE
- 1
- 1
- 3
- 6V
- INTVcc
- INTVcc
- ADJUSTABLE
- DC2038A-A
- LTC4162EUFD-LAD
- DC2038A-J
- LTC4162EUFD-LADM
- *
- *
- 6
- *
- 12V
- *
- *
- VCC2P5
- *
- 4.0V FIXED
- DC2038A-B
- LTC4162EUFD-L40
- DC2038A-K
- LTC4162EUFD-L40M
- *
- 2
- 2
- INTVcc
- LI-ION
- 3
- 3
- 9
- 18V
- INTVcc
- GND
- 4.1V FIXED
- DC2038A-C
- LTC4162EUFD-L41
- DC2038A-L
- LTC4162EUFD-L41M
- 4
- 4
- 12
- 24V
- VCC2P5
- INTVcc
- 4.2V FIXED
- DC2038A-D
- LTC4162EUFD-L42
- DC2038A-M
- LTC4162EUFD-L42M
- 5
- 5
- -
- VCC2P5
- VCC2P5
- ADJUSTABLE
- DC2038A-E
- LTC4162EUFD-FAD
- DC2038A-N
- LTC4162EUFD-FADM
- DISALLOWED
- 6
- 6
- DISALLOWED
- -
- VCC2P5
- GND
- LIFEPO4
- 3.6V FIXED
- DC2038A-F
- LTC4162EUFD-FST
- DC2038A-O
- LTC4162EUFD-FSTM
- 35V/3.2A MULTI-CELL STEP-DOWN BATTERY
- 7
- 7
- DISALLOWED
- -
- GND
- INTVcc
- 3.8V FIXED
- DC2038A-G
- LTC4162EUFD-FFS
- DC2038A-P
- LTC4162EUFD-FFSM
- CHARGER WITH POWERPATH AND I2C TELEMETRY
- ADJUSTABLE
- DC2038A-H
- LTC4162EUFD-SAD
- DC2038A-Q
- LTC4162EUFD-SADM
- 8
- 8
- DISALLOWED
- -
- GND
- VCC2P5
- LEAD
  ACID
- DISALLOWED
- 9
- -
- GND
- GND
- FIXED
- DC2038A-I
- LTC4162EUFD-SST
- DC2038A-R
- LTC4162EUFD-SSTM
- DISALLOWED
- * SEE TABLE
- 35V/3.2A MULTI-CELL STEP-DOWN BATTERY
- CHARGER WITH POWERPATH AND I2C TELEMETRY
- * SEE TABLE
